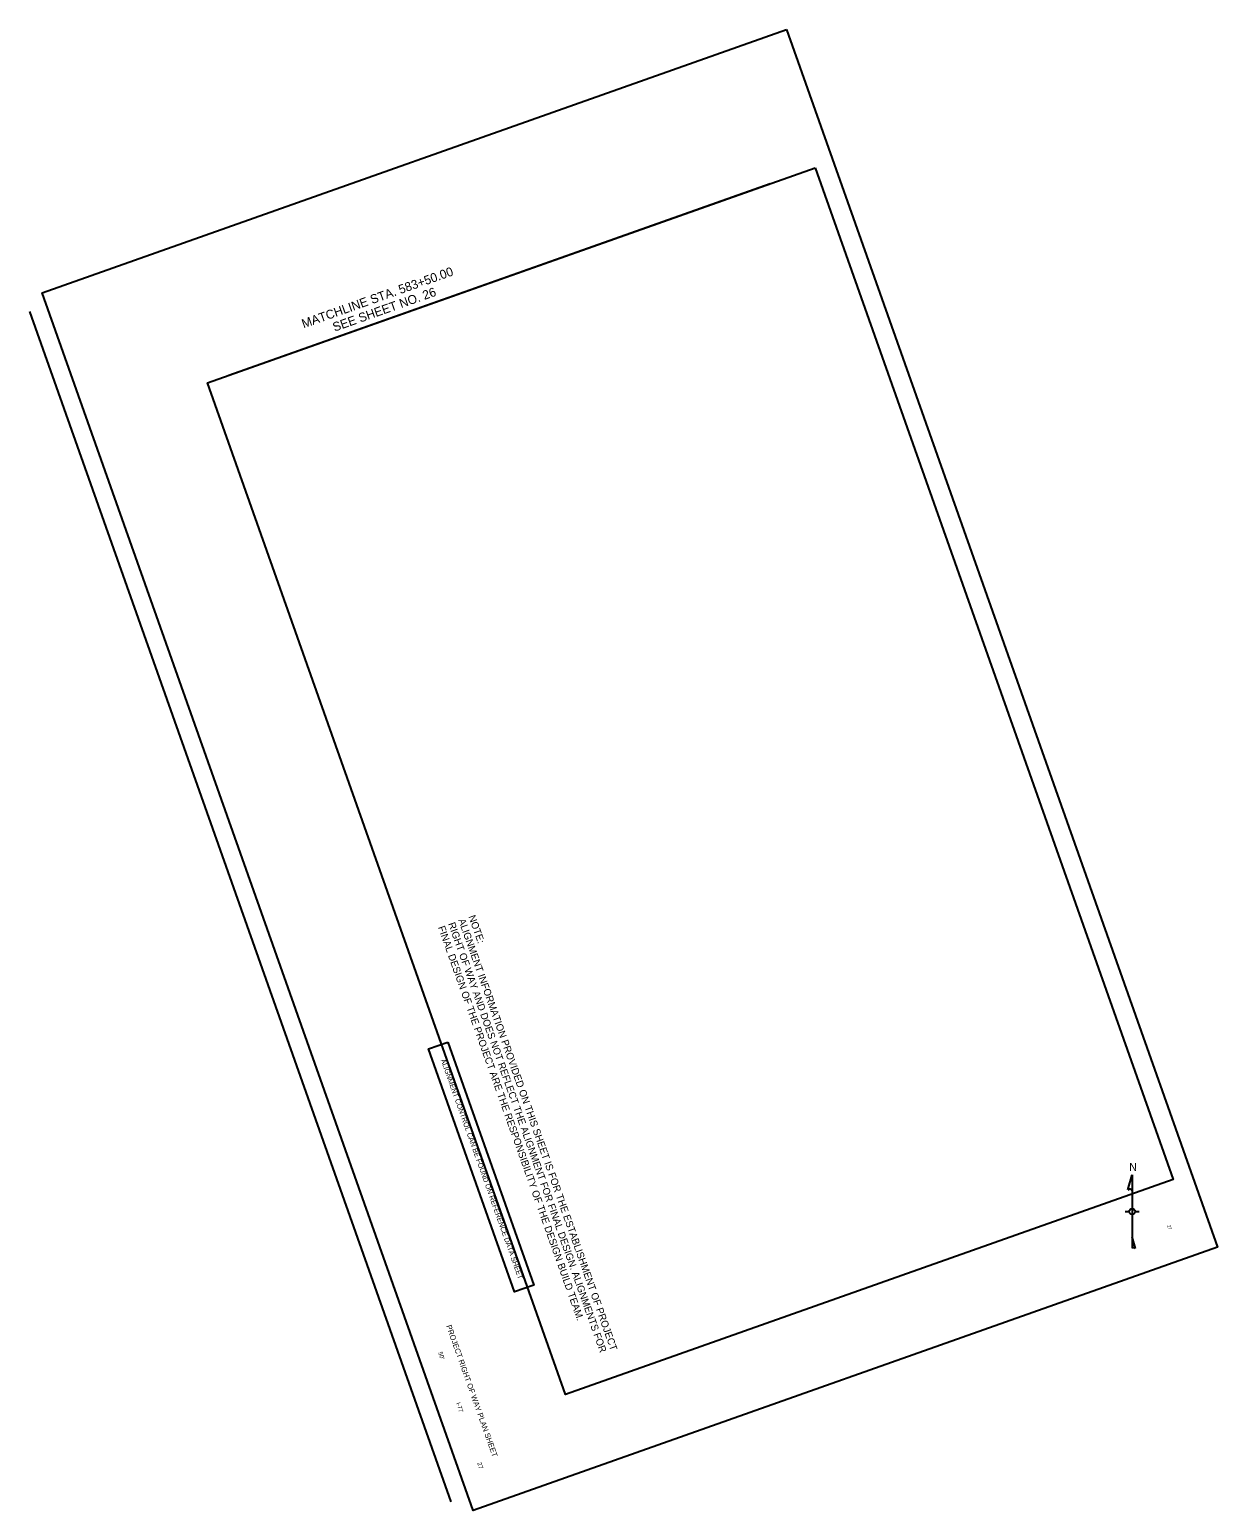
# Model space of a CAD drawing. Extents: x 2006190 to 2007845, y 1133293 to 1135356.
import ezdxf

# ---------------------------------------------------------------- set-up
doc = ezdxf.new("R2010")
doc.units = 0
for name, color, linetype in [('North Arrow', 7, 'Continuous'), ('RD_SHT_IplotShp', 7, 'Continuous'), ('RD_SHT_MatchLine', 7, 'Continuous'), ('RD_SHT_Misc1', 7, 'Continuous'), ('RD_SHT_ShtClip', 7, 'Continuous'), ('RD_SHT_TX', 7, 'Continuous')]:
    doc.layers.add(name, color=color, linetype=linetype)

msp = doc.modelspace()

# ---------------------------------------------------------------- linework, layer by layer
at = {"layer": 'North Arrow'}
for p, q in [((2007719.9, 1133739.2), (2007725.8, 1133760.2)), ((2007725.8, 1133760.2), (2007725.8, 1133738)), ((2007725.8, 1133760.2), (2007725.8, 1133658)), ((2007716.1, 1133709.1), (2007721.8, 1133709.1)), ((2007729.8, 1133709.1), (2007735.5, 1133709.1)), ((2007725.8, 1133673.8), (2007725.8, 1133658)), ((2007730.3, 1133657.7), (2007725.8, 1133673.8))]:
    msp.add_line(p, q, dxfattribs=at)
msp.add_circle((2007725.8, 1133709.1), 4.02, dxfattribs=at)
for centre, radius, start, end in [((2007722.5, 1133736.7), 3.59, 22.3707, 136.1387), ((2007727.9, 1133655.5), 3.3, 43.3397, 130.5607)]:
    msp.add_arc(centre, radius, start, end, dxfattribs=at)
at = {"layer": 'RD_SHT_IplotShp'}
msp.add_lwpolyline([(2007244.2, 1135356.5), (2007844.5, 1133659.5), (2006807.5, 1133292.7), (2006207.2, 1134989.6)], close=True, dxfattribs=at)
at = {"layer": 'RD_SHT_MatchLine'}
msp.add_line((2007221.5, 1135141.4), (2006467.3, 1134874.6), dxfattribs=at)
at = {"layer": 'RD_SHT_ShtClip'}
msp.add_lwpolyline([(2007284.4, 1135163.6), (2007783.1, 1133753.9), (2006936.5, 1133454.4), (2006437.8, 1134864.1)], close=True, dxfattribs=at)
at = {"layer": 'RD_SHT_TX'}
msp.add_line((2006189.8, 1134963.7), (2006776.8, 1133304.5), dxfattribs=at)
msp.add_lwpolyline([(2006772.5, 1133945.2), (2006892.3, 1133606.6), (2006865.5, 1133597.2), (2006745.7, 1133935.8)], close=True, dxfattribs=at)

# ---------------------------------------------------------------- texts
at = {"layer": 'North Arrow'}
msp.add_text('N', height=11.1, dxfattribs=at).set_placement((2007721.7, 1133765.7))
at = {"layer": 'RD_SHT_MatchLine'}
for s, p in [('MATCHLINE STA. 583+50.00', (2006571.5, 1134940.1)), ('SEE SHEET NO. 26', (2006614.6, 1134935.4))]:
    msp.add_text(s, height=12.5, rotation=19.482, dxfattribs=at).set_placement(p)
at = {"layer": 'RD_SHT_Misc1'}
for s, p in [('FINAL DESIGN OF THE PROJECT ARE THE RESPONSIBILITY OF THE DESIGN BUILD TEAM.', (2006758.6, 1134105.3)), ('RIGHT OF WAY AND DOES NOT REFLECT THE ALIGNMENT FOR FINAL DESIGN. ALIGNMENTS FOR', (2006772.7, 1134110.3)), ('ALIGNMENT INFORMATION PROVIDED ON THIS SHEET IS FOR THE ESTABLISHMENT OF PROJECT', (2006786.9, 1134115.3)), ('NOTE:', (2006801, 1134120.3))]:
    msp.add_text(s, height=10, rotation=289.482, dxfattribs=at).set_placement(p)
at = {"layer": 'RD_SHT_TX'}
for s, height, p in [('ALIGNMENT CONTROL CAN BE FOUND ON REFERENCE DATA SHEET', 7, (2006762.4, 1133920.6)), ('27', 4.5, (2007774.5, 1133689.5)), ('PROJECT RIGHT OF WAY PLAN SHEET', 7.5, (2006770, 1133549.7)), ("50'", 6, (2006758.9, 1133512.5)), ('I-77', 6, (2006783.8, 1133442)), ('27', 6, (2006813.3, 1133358.6))]:
    msp.add_text(s, height=height, rotation=289.482, dxfattribs=at).set_placement(p)

doc.saveas('drawing.dxf')
